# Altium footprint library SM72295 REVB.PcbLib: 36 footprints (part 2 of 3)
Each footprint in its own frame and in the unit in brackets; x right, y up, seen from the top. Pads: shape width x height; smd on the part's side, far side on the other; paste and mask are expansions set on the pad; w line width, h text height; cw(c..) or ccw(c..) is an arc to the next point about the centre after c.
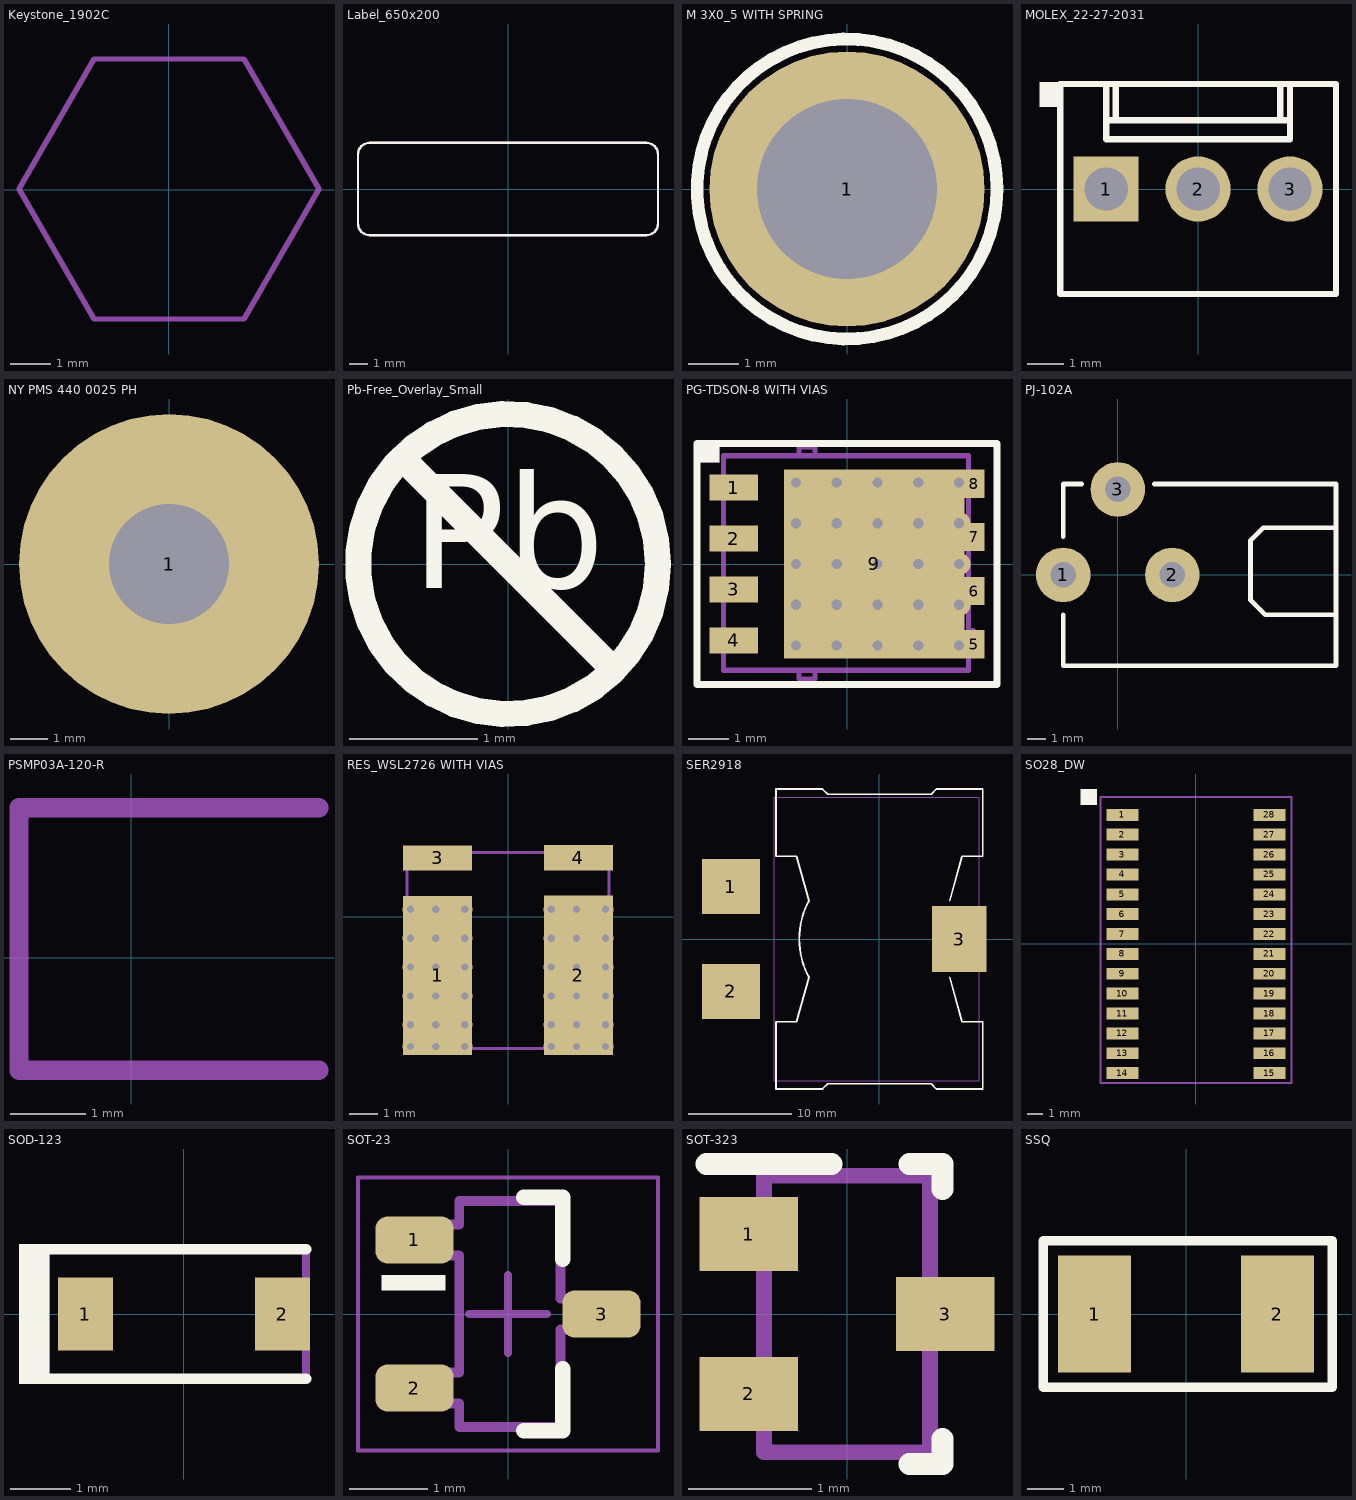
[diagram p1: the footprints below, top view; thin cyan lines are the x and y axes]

## Keystone_1902C [mil] "Hex Standoff, 4-40 threaded, nylon"
height 500
Mechanical 5:
  lines w5: -145.29,0.49 -72.56,126.47 72.92,126.47 145.65,0.49 72.92,-125.49 -72.56,-125.49 -145.29,0.49
  text ".Designator" at -60,-20 h40
3D body: height 501, standoff 1, extent -144.95,-125.98 146,125.98

## Label_650x200 [mil] "Thermal Transfer Label"
height 1
Top Overlay:
  lines w5: -325,-75 ccw(c-300,-75) -300,-100 300,-100 ccw(c300,-75) 325,-75 325,75 ccw(c300,75) 300,100 -300,100 ccw(c-300,75) -325,75 -325,-75
Mechanical 5:
  lines w5: -325,-75 ccw(c-300,-75) -300,-100 300,-100 ccw(c300,-75) 325,-75 325,75 ccw(c300,75) 300,100 -300,100 ccw(c-300,75) -325,75 -325,-75
  text ".Designator" at -60,-20 h30
3D body: height 1, standoff 0, extent -325.51,-100.51 325.51,100.51

## M 3X0_5 WITH SPRING [mm] "M 3X0.5 SCREW WITH ATS-PPS-06 SPRING"
height 2.4
pads (1):
  round 5.5 hole 3.6: 1(0,0)
Top Overlay:
  circle w0.254: c0,0 r3
Mechanical 5:
  text ".Designator" at -1.27,-0.381 h0.76
3D body: height 2.5, standoff 0, extent -3.146,-3.1 3.1,3.1

## MOLEX_22-27-2031 [mm] "MOLEX"
height 12.05
pads (3):
  rect 1.8x1.8 hole 1.2: 1(-2.54,0)
  round 1.8 hole 1.2: 2(0,0) 3(2.54,0)
Top Overlay:
  region: -3.875,2.26 -3.875,2.96 -4.375,2.96 -4.375,2.26
  lines w0.178: -2.54,1.9 -2.54,1.37 2.54,1.37 2.54,1.9 ; -2.54,1.9 -2.54,2.9 ; -2.54,1.9 -2.267,1.9 ; -2.54,2.9 -3.81,2.9 -3.81,-2.9 3.81,-2.9 3.81,2.9 2.54,2.9 ; -2.54,2.9 -2.267,2.9 ; -2.267,1.9 -2.267,2.9 ; -2.267,1.9 2.267,1.9 ; -2.267,2.9 2.267,2.9 ; 2.267,1.9 2.267,2.9 ; 2.267,1.9 2.54,1.9 ; 2.267,2.9 2.54,2.9 ; 2.54,1.9 2.54,2.9
Mechanical 5:
  lines w0.127: -2.54,1.9 -2.267,1.9 ; -2.54,1.9 -2.54,2.9 ; -2.54,1.9 -2.54,1.37 2.54,1.37 2.54,1.9 ; -2.54,2.9 -2.267,2.9 ; -2.54,2.9 -3.81,2.9 -3.81,-2.9 3.81,-2.9 3.81,2.9 2.54,2.9 ; -2.267,1.9 2.267,1.9 ; -2.267,1.9 -2.267,2.9 ; -2.267,2.9 2.267,2.9 ; 2.267,1.9 2.54,1.9 ; 2.267,1.9 2.267,2.9 ; 2.267,2.9 2.54,2.9 ; 2.54,1.9 2.54,2.9
  text ".Designator" at -0.635,-0.381 h0.76
3D body: height 11.72, standoff -3.54, extent -3.81,-2.9 3.81,2.9

## NY PMS 440 0025 PH [mm] "4-40 nylon screw and mounting hole"
height 1.905
pads (1):
  round 8 hole 3.2: 1(0,0)
Mechanical 5:
  circle w0.127: c0,0 r3.789
  text ".Designator" at -1.524,-0.508 h1.02
3D body: height 2.69, standoff -8.74, extent -3.302,-3.3 3.296,3.3

## Pb-Free_Overlay_Small [mil]
Top Overlay:
  circle w8: c0,0 r46
  lines w8: -32.53,32.53 32.53,-32.53
  text "Pb" at -29.6,-18.9 h60

## PG-TDSON-8 WITH VIAS [mm] "Infineon recommended land pattern"
height 1.1
pads (9):
  rect 1.2x0.65 smd: 1(-2.825,1.905) 2(-2.825,0.635) 3(-2.825,-0.635) 4(-2.825,-1.905)
  rect 0.5x0.7 smd: 5(3.175,-2) 6(3.175,-0.675) 7(3.175,0.675) 8(3.175,2)
  rect 4.5x4.7 smd paste-2.25: 9(0.675,0)
via 2.794,2.032 diameter 0.559 hole 0.254
via 2.794,1.016 diameter 0.559 hole 0.254
via 2.794,0 diameter 0.559 hole 0.254
via 2.794,-1.016 diameter 0.559 hole 0.254
via 2.794,-2.032 diameter 0.559 hole 0.254
via 1.778,-2.032 diameter 0.559 hole 0.254
via 0.762,-2.032 diameter 0.559 hole 0.254
via 1.778,-1.016 diameter 0.559 hole 0.254
via 1.778,2.032 diameter 0.559 hole 0.254
via 1.778,1.016 diameter 0.559 hole 0.254
via 0.762,2.032 diameter 0.559 hole 0.254
via 0.762,1.016 diameter 0.559 hole 0.254
via 0.762,-1.016 diameter 0.559 hole 0.254
via -0.254,-2.032 diameter 0.559 hole 0.254
via -0.254,-1.016 diameter 0.559 hole 0.254
via -0.254,1.016 diameter 0.559 hole 0.254
via -0.254,2.032 diameter 0.559 hole 0.254
via -1.27,2.032 diameter 0.559 hole 0.254
via -1.27,1.016 diameter 0.559 hole 0.254
via -1.27,-2.032 diameter 0.559 hole 0.254
via -1.27,-1.016 diameter 0.559 hole 0.254
via 1.778,0 diameter 0.559 hole 0.254
via 0.762,0 diameter 0.559 hole 0.254
via -0.254,0 diameter 0.559 hole 0.254
via -1.27,0 diameter 0.559 hole 0.254
Top Overlay:
  rectangle: -3.74,2.527 -3.175,2.975
  lines w0.178: -3.74,-3 -3.74,0 -3.74,3 0.105,3 3.74,3 3.74,0 3.74,-3 -0.105,-3 -3.74,-3
Top Paste:
  rectangle: -1.475,0.95 -0.242,2.25
  rectangle: 0.058,0.95 1.291,2.25
  rectangle: 1.591,0.95 2.824,2.25
  rectangle: -1.475,-0.65 -0.242,0.65
  rectangle: 0.058,-0.65 1.291,0.65
  rectangle: 1.591,-0.65 2.824,0.65
  rectangle: 1.591,-2.25 2.824,-0.95
  rectangle: 0.058,-2.25 1.291,-0.95
  rectangle: -1.475,-2.25 -0.242,-0.95
Mechanical 5:
  rectangle: -3.74,2.527 -3.175,2.975
  lines w0.127: -3.075,-2.1 -3.2,-2.1 -3.2,-1.66 -3.075,-1.66 ; -3.075,-0.83 -3.2,-0.83 -3.2,-0.39 -3.075,-0.39 ; -3.075,0.44 -3.2,0.44 -3.2,0.88 -3.075,0.88 ; -3.075,1.71 -3.2,1.71 -3.2,2.15 -3.075,2.15 ; -1.2,-2.65 -1.2,-2.87 -0.8,-2.87 -0.8,-2.65 ; -1.2,2.7 -1.2,2.92 -0.8,2.92 -0.8,2.7 ; 3.025,-2.1 3.15,-2.1 3.15,-1.66 3.025,-1.66 ; 3.025,-0.83 3.15,-0.83 3.15,-0.39 3.025,-0.39 ; 3.025,0.44 3.15,0.44 3.15,0.88 3.025,0.88 ; 3.025,1.71 3.15,1.71 3.15,2.15 3.025,2.15 ; -3.075,-2.65 3.025,-2.65 3.025,2.7 -3.075,2.7 -3.075,-2.65
  text ".Designator" at 0.635,-1.143 h1.02
3D body: height 1.1, standoff 0, extent -3.175,-2.895 3.175,2.895

## PJ-102A [mm] "CU INC PJ-102A"
height 11
pads (3):
  round 3 hole 1.4: 1(-3,0) 2(3,0) 3(0,4.7)
Top Overlay:
  lines w0.254: -3,-2.2 -3,-5 12,-5 12,5 2,5 ; -3,2.1 -3,5 -2,5 ; 12,-2.2 8.1,-2.2 7.3,-1.4 7.3,1.9 8,2.6 8.7,2.6 12,2.6
Mechanical 5:
  text ".Designator" at 5.842,2.54 h0.76
3D body: height 11, standoff 0, extent -3,-5 12,5

## PSMP03A-120-R [mil] "PHIHONG WALL WART 12V 230MA"
height 1574.8
Mechanical 5:
  lines w10: 98.43,-59.06 -59.06,-59.06 -59.06,78.74 98.43,78.74
  text ".Designator" at 0,-3.94 h30

## RES_WSL2726 WITH VIAS [mm] "Vishay Dale"
height 3.2
pads (4):
  rect 2.44x5.6 smd: 1(-2.48,-2.07) 2(2.48,-2.065)
  rect 2.44x0.89 smd: 3(-2.48,2.065) 4(2.48,2.07)
via 1.524,0.254 diameter 0.559 hole 0.254
via 2.413,-0.762 diameter 0.559 hole 0.254
via 2.413,-1.778 diameter 0.559 hole 0.254
via 2.413,-2.794 diameter 0.559 hole 0.254
via 3.429,0.254 diameter 0.559 hole 0.254
via 2.413,0.254 diameter 0.559 hole 0.254
via 2.413,-3.81 diameter 0.559 hole 0.254
via 2.413,-4.572 diameter 0.559 hole 0.254
via 3.429,-3.81 diameter 0.559 hole 0.254
via 3.429,-2.794 diameter 0.559 hole 0.254
via 3.429,-1.778 diameter 0.559 hole 0.254
via 3.429,-4.572 diameter 0.559 hole 0.254
via 1.524,-4.572 diameter 0.559 hole 0.254
via 1.524,-3.81 diameter 0.559 hole 0.254
via 1.524,-2.794 diameter 0.559 hole 0.254
via 1.524,-1.778 diameter 0.559 hole 0.254
via 1.524,-0.762 diameter 0.559 hole 0.254
via 3.429,-0.762 diameter 0.559 hole 0.254
via -1.524,0.254 diameter 0.559 hole 0.254
via -3.429,0.254 diameter 0.559 hole 0.254
via -3.429,-0.762 diameter 0.559 hole 0.254
via -3.429,-1.778 diameter 0.559 hole 0.254
via -3.429,-2.794 diameter 0.559 hole 0.254
via -3.429,-3.81 diameter 0.559 hole 0.254
via -3.429,-4.572 diameter 0.559 hole 0.254
via -1.524,-4.572 diameter 0.559 hole 0.254
via -1.524,-3.81 diameter 0.559 hole 0.254
via -1.524,-2.794 diameter 0.559 hole 0.254
via -1.524,-1.778 diameter 0.559 hole 0.254
via -1.524,-0.762 diameter 0.559 hole 0.254
via -2.54,0.254 diameter 0.559 hole 0.254
via -2.54,-0.762 diameter 0.559 hole 0.254
via -2.54,-1.778 diameter 0.559 hole 0.254
via -2.54,-2.794 diameter 0.559 hole 0.254
via -2.54,-3.81 diameter 0.559 hole 0.254
via -2.54,-4.572 diameter 0.559 hole 0.254
Mechanical 5:
  lines w0.1: -3.55,-4.65 -3.55,2.25 3.55,2.25 3.55,-4.65 -3.55,-4.65
  text ".Designator" at -1.016,-2.032 h0.76
3D body: height 3.22, standoff 0.02, extent -3.55,-4.45 3.55,2.45

## SER2918 [mm] "Coilcraft recommended land pattern.  Document 644-2, rev 12/12/08"
height 17.78
pads (3):
  rect 5.59x5.33 smd: 1(-14.355,5.075) 2(-14.355,-5.075)
  rect 5.28x6.35 smd: 3(7.72,0)
Top Overlay:
  lines w0.178: 6.8,-3.7 8,-8 10,-8 10,-14.5 5.5,-14.5 5,-14 0,-14 -5,-14 -5.5,-14.5 -10,-14.5 -10,-8 -8,-8 -6.8,-3.7 cw(c0,0) -7.741,0 cw(c0,0) -6.8,3.7 -8,8 -10,8 -10,14.5 -5.5,14.5 -5,14 0,14 5,14 5.5,14.5 10,14.5 10,8 8,8 6.8,3.7
Mechanical 5:
  lines w0.102: -10.16,-13.716 9.652,-13.716 9.652,13.716 -9.652,13.716 -10.16,13.716 -10.16,-13.716
  text ".Designator" at -1.778,-0.508 h1.02
3D body: height 17.78, standoff 0, extent -16.8,-13.95 11.031,13.95

## SO28_DW [mil]
pads (28):
  rect 80x30 smd: 1(-185,325) 2(-185,275) 3(-185,225) 4(-185,175) 5(-185,125) 6(-185,75) 7(-185,25) 8(-185,-25) 9(-185,-75) 10(-185,-125) 11(-185,-175) 12(-185,-225) 13(-185,-275) 14(-185,-325) 15(185,-325) 16(185,-275) 17(185,-225) 18(185,-175) 19(185,-125) 20(185,-75) 21(185,-25) 22(185,25) 23(185,75) 24(185,125) 25(185,175) 26(185,225) 27(185,275) 28(185,325)
Top Overlay:
  region: -250,350 -250,390 -290,390 -290,350
Mechanical 5:
  lines w5: -240,370 -240,-350 240,-350 240,370 ; -240,370.1 240,370.1
  text ".Designator" at -35,-20 h40
  text "*" at -124.57,310 h30

## SOD-123 [mm] "On Semi recommended land pattern"
height 1.35
pads (2):
  rect 0.915x1.22 smd: 1(-1.637,0) 2(1.637,0)
Top Overlay:
  rectangle: -2.743,-1.168 -2.235,1.168
  lines w0.178: -2.413,-1.079 2.032,-1.079 ; -2.413,1.079 2.032,1.079
Mechanical 5:
  rectangle: -2.743,-1.168 -2.235,1.168
  lines w0.127: -2.413,-1.079 2.032,-1.079 2.032,1.079 -2.413,1.079
  text ".Designator" at 0.508,0.381 h0.76
3D body: height 1.35, standoff 0, extent -1.932,-0.9 1.932,0.9

## SOT-23 [mm] "SOT23, 3-Leads, Body 2.9x1.3mm, Pitch 0.95mm, Lead Span 2.5mm, IPC Medium Density"
height 1.1
pads (3):
  rrect50% 1x0.6 smd: 1(-1.2,0.95) 2(-1.2,-0.95) 3(1.2,0)
Top Overlay:
  rectangle: -1.625,0.3 -0.8,0.5
  lines w0.2: 0.2,-1.5 0.7,-1.5 0.7,-0.7 ; 0.2,1.5 0.7,1.5 0.7,0.7
Mechanical 5:
  lines w0.127: -1.16,-1.15 -1.16,-0.75 -0.625,-0.75 -0.625,0.75 -1.16,0.75 -1.16,1.15 -0.625,1.15 -0.625,1.45 0.675,1.45 0.675,0.2 1.21,0.2 1.21,-0.2 0.675,-0.2 0.675,-1.45 -0.625,-1.45 -0.625,-1.15 -1.16,-1.15
  text ".Designator" at 0.381,-0.762 h0.64
Mechanical 15:
  lines w0.05: -1.925,-1.75 1.925,-1.75 1.925,1.75 -1.925,1.75 -1.925,-1.75
  lines w0.1: -0.5,0 0.5,0 ; 0,-0.5 0,0.5
3D body: height 1, standoff 0, extent -1.16,-1.45 1.21,1.45

## SOT-323 [mm] "Zetex recommended land pattern.  March 2007"
height 1.1
pads (3):
  rect 0.8x0.6 smd: 1(-0.8,0.65) 2(-0.8,-0.65) 3(0.8,0)
Top Overlay:
  lines w0.178: -1.143,1.219 -0.127,1.219 ; 0.508,-1.219 0.775,-1.219 0.775,-1.016 ; 0.508,1.219 0.775,1.219 0.775,1.016
Mechanical 5:
  lines w0.127: -1.125,-0.8 -0.975,-0.8 -0.935,-0.8 -0.884,-0.8 -0.725,-0.8 -0.675,-0.8 -0.675,-0.5 -0.725,-0.5 -0.884,-0.5 -0.935,-0.5 -0.975,-0.5 -1.125,-0.5 -1.125,-0.8 ; -1.125,0.5 -0.975,0.5 -0.935,0.5 -0.884,0.5 -0.725,0.5 -0.675,0.5 -0.675,0.8 -0.725,0.8 -0.884,0.8 -0.935,0.8 -0.975,0.8 -1.125,0.8 -1.125,0.5 ; -0.675,-1.125 0.675,-1.125 0.675,1.125 -0.675,1.125 -0.675,-1.125 ; 0.675,-0.15 0.675,0.15 0.725,0.15 0.884,0.15 0.935,0.15 0.975,0.15 1.125,0.15 1.125,-0.15 0.975,-0.15 0.935,-0.15 0.884,-0.15 0.725,-0.15 0.675,-0.15
  text ".Designator" at -0.25,0.925 h0.51
3D body: height 1.13, standoff 0.02, extent -1.125,-1.125 1.125,1.125

## SSQ [mm] "BEL FUSE INC SSQ FUSE"
height 2.54
pads (2):
  rect 2x3.2 smd: 1(-2.5,0) 2(2.5,0)
Top Overlay:
  lines w0.254: -3.9,-2 -3.9,2 4,2 4,-2 -3.9,-2
Mechanical 5:
  text ".Designator" at -0.254,0.635 h0.76
3D body: height 2.54, standoff 0, extent -3.9,-2 4,2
